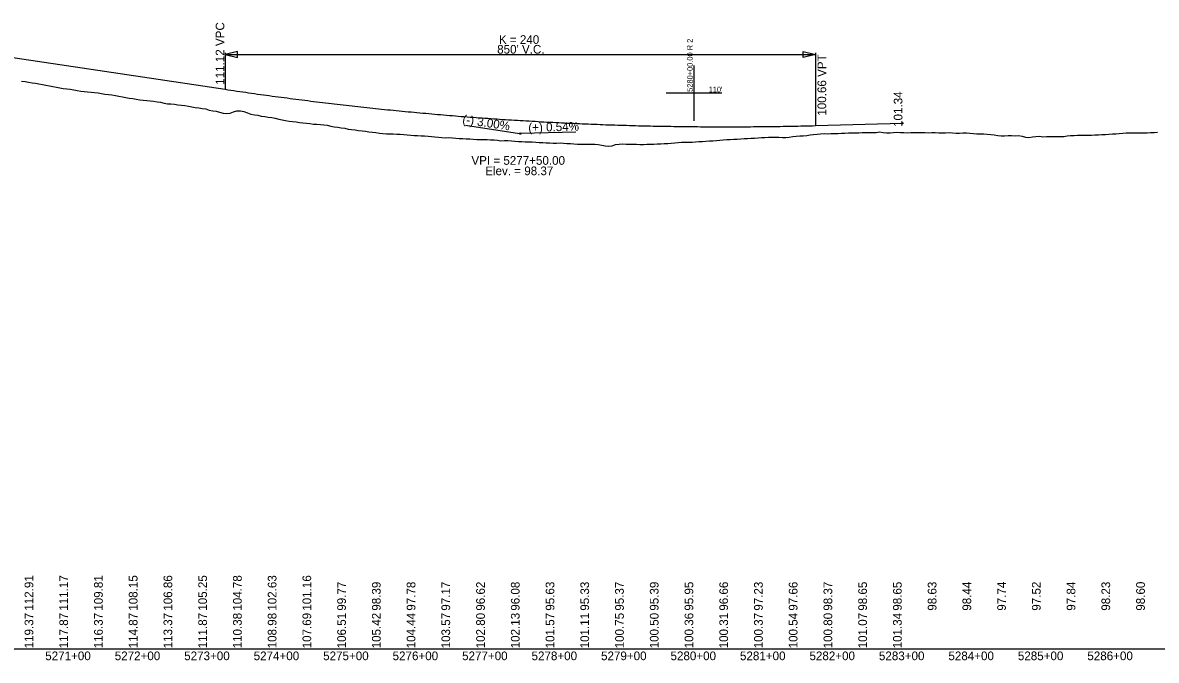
# Model space of a CAD drawing. Extents: x 2147288 to 2220488, y 740833 to 759333.
# Drawn here: x 2159415 to 2161047, y 750067 to 750985 of the extents above; entities that cross this region are included whole.
import ezdxf

# ---------------------------------------------------------------- set-up
doc = ezdxf.new("R2010")
doc.units = 0
for name, color, linetype in [('RD_DDB_GradeTX', 7, 'Continuous'), ('RD_DDB_Profile_EX', 7, 'Continuous'), ('RD_DDB_Profile_Lbl', 7, 'Continuous'), ('RD_DDB_Profile_PR', 7, 'Continuous'), ('RD_DDB_StaTX', 7, 'Continuous'), ('RD_DDB_StripGrade', 7, 'Continuous'), ('RD_DDB_VCLbl', 7, 'Continuous'), ('RD_GPK_Profile_Cell', 7, 'Continuous')]:
    doc.layers.add(name, color=color, linetype=linetype)

msp = doc.modelspace()

# ---------------------------------------------------------------- linework, layer by layer
at = {"layer": 'RD_DDB_GradeTX'}
for p, q in [((2160052, 750837.1), (2160130.1, 750825.4)), ((2160211.1, 750827.4), (2160132.1, 750825.3))]:
    msp.add_line(p, q, dxfattribs=at)
for centre in [(2160681.1, 750840.1), (2160131.1, 750825.3)]:
    msp.add_circle(centre, 1, dxfattribs=at)
at = {"layer": 'RD_DDB_Profile_EX'}
for points in [[(2159413.3, 750900.9), (2159418.3, 750900), (2159423.3, 750899.2), (2159428.3, 750898.4), (2159433.3, 750897.6), (2159438.3, 750896.8), (2159443.3, 750895.9), (2159448.3, 750894.9), (2159453.3, 750893.9), (2159458.3, 750892.8), (2159463.3, 750891.8), (2159468.3, 750891), (2159473.3, 750890.3), (2159478.3, 750889.7), (2159483.3, 750889), (2159488.3, 750888.2), (2159493.3, 750887.3), (2159498.3, 750886.4), (2159503.3, 750886), (2159508.3, 750885.5), (2159513.3, 750885), (2159518.3, 750884.5), (2159523.3, 750883.7), (2159528.3, 750882.9), (2159533.3, 750882.1), (2159538.3, 750881.5)], [(2159538.3, 750881.5), (2159543.3, 750880.8), (2159548.3, 750879.9), (2159553.3, 750878.9), (2159558.3, 750877.9), (2159563.3, 750877), (2159568.3, 750876.3), (2159573.3, 750875.6), (2159578.3, 750874.6), (2159583.3, 750873.8), (2159588.3, 750873.4), (2159593.3, 750872.9), (2159598.3, 750872.5), (2159603.3, 750871.9), (2159608.3, 750871.1), (2159613.3, 750870.2), (2159618.3, 750868.9), (2159623.3, 750867.8), (2159628.3, 750867.8), (2159633.3, 750867.7), (2159638.3, 750866.8), (2159643.3, 750866.1), (2159648.3, 750865.4), (2159653.3, 750864.6), (2159658.3, 750863.8), (2159663.3, 750862.9), (2159668.3, 750862.3), (2159673.3, 750861.5), (2159678.3, 750860.7), (2159683.3, 750858.9), (2159688.3, 750857.9), (2159693.3, 750857.3), (2159698.3, 750856.1), (2159703.3, 750854.5), (2159708.3, 750853.9), (2159713.3, 750854.7), (2159718.3, 750856.5), (2159723.3, 750857.8), (2159728.3, 750857.9), (2159733.3, 750856.8), (2159738.3, 750855.1), (2159743.3, 750853.1), (2159748.3, 750852.2), (2159753.3, 750851.5), (2159758.3, 750850.5), (2159763.3, 750849.6), (2159768.3, 750849), (2159773.3, 750848.2), (2159778.3, 750847.2), (2159783.3, 750846.1), (2159788.3, 750845), (2159793.3, 750844.2), (2159798.3, 750843.3), (2159803.3, 750842.6), (2159808.3, 750841.9), (2159813.3, 750841.4), (2159818.3, 750840.9), (2159823.3, 750840.4), (2159828.3, 750839.6), (2159833.3, 750839), (2159838.3, 750838.6), (2159843.3, 750838.2), (2159848.3, 750837.7), (2159853.3, 750837.1), (2159858.3, 750835.8), (2159863.3, 750834.9), (2159868.3, 750834.3), (2159873.3, 750833.5), (2159878.3, 750832.9), (2159883.3, 750831.8), (2159888.3, 750831.1), (2159893.3, 750830.5), (2159898.3, 750829.6), (2159903.3, 750829.1), (2159908.3, 750828.6), (2159913.3, 750827.7), (2159918.3, 750827.3), (2159923.3, 750826.8), (2159928.3, 750825.7), (2159933.3, 750825.1), (2159938.3, 750825), (2159943.3, 750824.8), (2159948.3, 750824.7), (2159953.3, 750824.5), (2159958.3, 750824.2), (2159963.3, 750823.7), (2159968.3, 750823.5), (2159973.3, 750822.8), (2159978.3, 750822.4), (2159983.3, 750822.3), (2159988.3, 750822.2), (2159993.3, 750821.8), (2159998.3, 750821.4), (2160003.3, 750821), (2160008.3, 750820.6), (2160013.3, 750820), (2160018.3, 750819.8), (2160023.3, 750819.3), (2160028.3, 750819.4), (2160033.3, 750819.1), (2160038.3, 750818.6)], [(2160538.3, 750822.2), (2160543.3, 750822.4), (2160548.3, 750823.3), (2160553.3, 750824.1), (2160558.3, 750824.3), (2160563.3, 750825), (2160568.3, 750825.4), (2160573.3, 750825), (2160578.3, 750825.1), (2160583.3, 750825.3), (2160588.3, 750825.5), (2160593.3, 750825.7), (2160598.3, 750826), (2160603.3, 750826.2), (2160608.3, 750826.2), (2160613.3, 750826.3), (2160618.3, 750826.5), (2160623.3, 750826.6), (2160628.3, 750826.7), (2160633.3, 750826.7), (2160638.3, 750826.7), (2160643.3, 750827), (2160648.3, 750827.5), (2160653.3, 750826.9), (2160658.3, 750826.4), (2160663.3, 750826.4), (2160668.3, 750826.6), (2160673.3, 750827.1), (2160678.3, 750826.7), (2160683.3, 750826.7), (2160688.3, 750826.5), (2160693.3, 750826.8), (2160698.3, 750827), (2160703.3, 750827), (2160708.3, 750826.9), (2160713.3, 750826.7), (2160718.3, 750826.5), (2160723.3, 750826.7), (2160728.3, 750826.7), (2160733.3, 750826.5), (2160738.3, 750826.4), (2160743.3, 750826.5), (2160748.3, 750826.6), (2160753.3, 750826.2), (2160758.3, 750826), (2160763.3, 750826), (2160768.3, 750826.2), (2160773.3, 750826.1), (2160778.3, 750825.8), (2160783.3, 750825.5), (2160788.3, 750825), (2160793.3, 750824.8), (2160798.3, 750824.8), (2160803.3, 750824.6), (2160808.3, 750823.9), (2160813.3, 750823.2), (2160818.3, 750822.5), (2160823.3, 750822.2), (2160828.3, 750821.9), (2160833.3, 750822.3), (2160838.3, 750822.4), (2160843.3, 750822.2), (2160848.3, 750822.5), (2160853.3, 750821.4), (2160858.3, 750819.9), (2160863.3, 750819.6), (2160868.3, 750820.3), (2160873.3, 750821), (2160878.3, 750821.5), (2160883.3, 750820.7), (2160888.3, 750820.8), (2160893.3, 750820.8), (2160898.3, 750820.8), (2160903.3, 750820.9), (2160908.3, 750820.8), (2160913.3, 750820.9), (2160918.3, 750821.8), (2160923.3, 750822.4), (2160928.3, 750822.6), (2160933.3, 750822.7), (2160938.3, 750822.8), (2160943.3, 750822.8), (2160948.3, 750822.8), (2160953.3, 750823.1), (2160958.3, 750823.3), (2160963.3, 750823.5), (2160968.3, 750823.8), (2160973.3, 750823.8), (2160978.3, 750824.4), (2160983.3, 750824.7), (2160988.3, 750824.9), (2160993.3, 750825.4), (2160998.3, 750825.8), (2161003.3, 750826.3), (2161008.3, 750826.2), (2161013.3, 750826.5), (2161018.3, 750826.5), (2161023.3, 750826.4), (2161028.3, 750826.3), (2161033.3, 750826.5), (2161038.3, 750826.8)], [(2161038.3, 750826.8), (2161043.3, 750827), (2161048.3, 750827.2)], [(2160038.3, 750818.6), (2160043.3, 750818.2), (2160048.3, 750817.9), (2160053.3, 750817.8), (2160058.3, 750817.6), (2160063.3, 750817.3), (2160068.3, 750816.9), (2160073.3, 750816.7), (2160078.3, 750816.6), (2160083.3, 750816.5), (2160088.3, 750816.3), (2160093.3, 750816), (2160098.3, 750815.5), (2160103.3, 750815), (2160108.3, 750815.1), (2160113.3, 750815.1), (2160118.3, 750814.7), (2160123.3, 750814.4), (2160128.3, 750814), (2160133.3, 750813.7), (2160138.3, 750813.4), (2160143.3, 750813.1), (2160148.3, 750813.1), (2160153.3, 750813), (2160158.3, 750812.5), (2160163.3, 750812.2), (2160168.3, 750812.1), (2160173.3, 750811.9), (2160178.3, 750811.6), (2160183.3, 750811.6), (2160188.3, 750811.7), (2160193.3, 750811.5), (2160198.3, 750811), (2160203.3, 750810.7), (2160208.3, 750810.4), (2160213.3, 750810.1), (2160218.3, 750809.9), (2160223.3, 750809.9), (2160228.3, 750810), (2160233.3, 750810.1), (2160238.3, 750809.9), (2160243.3, 750809.6), (2160248.3, 750808.5), (2160253.3, 750807.6), (2160258.3, 750807.2), (2160263.3, 750807.6), (2160268.3, 750809.3), (2160273.3, 750809.9), (2160278.3, 750810.5), (2160283.3, 750810.1), (2160288.3, 750809.9), (2160293.3, 750809.9), (2160298.3, 750809.8), (2160303.3, 750809.6), (2160308.3, 750809.7), (2160313.3, 750809.9), (2160318.3, 750810.1), (2160323.3, 750810.2), (2160328.3, 750810.3), (2160333.3, 750810.4), (2160338.3, 750810.7), (2160343.3, 750811), (2160348.3, 750811.5), (2160353.3, 750811.9), (2160358.3, 750812.6), (2160363.3, 750812.7), (2160368.3, 750812.7), (2160373.3, 750812.8), (2160378.3, 750813), (2160383.3, 750813.3), (2160388.3, 750813.7), (2160393.3, 750813.9), (2160398.3, 750814.2), (2160403.3, 750814.6), (2160408.3, 750814.9), (2160413.3, 750815.2), (2160418.3, 750815.6), (2160423.3, 750816), (2160428.3, 750816.5), (2160433.3, 750816.9), (2160438.3, 750817.2), (2160443.3, 750817.4), (2160448.3, 750817.8), (2160453.3, 750818.1), (2160458.3, 750818.2), (2160463.3, 750818.5), (2160468.3, 750818.6), (2160473.3, 750819), (2160478.3, 750819.4), (2160483.3, 750819.7), (2160488.3, 750820.1), (2160493.3, 750819.9), (2160498.3, 750820.2), (2160503.3, 750819.9), (2160508.3, 750819.4), (2160513.3, 750819.4), (2160518.3, 750820.2), (2160523.3, 750820.9), (2160528.3, 750821.5), (2160533.3, 750821.9), (2160538.3, 750822.2)]]:
    msp.add_lwpolyline(points, dxfattribs=at)
at = {"layer": 'RD_DDB_Profile_PR'}
for p, q in [((2159381.1, 750937.8), (2159706.1, 750889)), ((2160556.1, 750836.7), (2160681.1, 750840.1))]:
    msp.add_line(p, q, dxfattribs=at)
msp.add_spline([(2159706.1, 750889), (2159723.1, 750886.5), (2159740.1, 750884), (2159757.1, 750881.6), (2159774.1, 750879.3), (2159791.1, 750877), (2159808.1, 750874.8), (2159825.1, 750872.6), (2159842.1, 750870.5), (2159859.1, 750868.5), (2159876.1, 750866.5), (2159893.1, 750864.6), (2159910.1, 750862.7), (2159927.1, 750860.9), (2159944.1, 750859.2), (2159961.1, 750857.5), (2159978.1, 750855.9), (2159995.1, 750854.4), (2160012.1, 750852.9), (2160029.1, 750851.4), (2160046.1, 750850), (2160063.1, 750848.7), (2160080.1, 750847.5), (2160097.1, 750846.3), (2160114.1, 750845.1), (2160131.1, 750844.1), (2160148.1, 750843.1), (2160165.1, 750842.1), (2160182.1, 750841.2), (2160199.1, 750840.4), (2160216.1, 750839.6), (2160233.1, 750838.9), (2160250.1, 750838.2), (2160267.1, 750837.6), (2160284.1, 750837.1), (2160301.1, 750836.6), (2160318.1, 750836.2), (2160335.1, 750835.9), (2160352.1, 750835.6), (2160369.1, 750835.3), (2160386.1, 750835.2), (2160403.1, 750835), (2160420.1, 750835), (2160437.1, 750835), (2160454.1, 750835.1), (2160471.1, 750835.2), (2160488.1, 750835.4), (2160505.1, 750835.6), (2160522.1, 750835.9), (2160539.1, 750836.3), (2160556.1, 750836.7)], degree=3, dxfattribs=at)
at = {"layer": 'RD_DDB_VCLbl'}
for p, q in [((2159706.1, 750941.5), (2159706.1, 750889)), ((2159706.1, 750939), (2160556.1, 750939)), ((2160556.1, 750941.5), (2160556.1, 750836.7))]:
    msp.add_line(p, q, dxfattribs=at)
for points in [[(2159724.1, 750943.5), (2159706.1, 750939), (2159724.1, 750934.5)], [(2160538.1, 750943.5), (2160556.1, 750939), (2160538.1, 750934.5)]]:
    msp.add_lwpolyline(points, close=True, dxfattribs=at)
at = {"layer": 'RD_GPK_Profile_Cell'}
for p, q in [((2160381.1, 750923.4), (2160381.1, 750843.4)), ((2160421.1, 750883.4), (2160341.1, 750883.4)), ((2148888.3, 750083.4), (2170488.3, 750083.4))]:
    msp.add_line(p, q, dxfattribs=at)

# ---------------------------------------------------------------- texts
at = {"layer": 'RD_DDB_GradeTX'}
for s, rotation, p in [('(-) 3.00%', 351.4692, (2160047.2, 750839.9)), ('(+) 0.54%', 1.5466, (2160142.8, 750827.6))]:
    msp.add_text(s, height=12.5, rotation=rotation, dxfattribs=at).set_placement(p)
at = {"layer": 'RD_DDB_Profile_Lbl'}
msp.add_text('101.34', height=12.5, rotation=90, dxfattribs=at).set_placement((2160681.1, 750834.8))
for s, p in [('VPI = 5277+50.00', (2160060.7, 750780.3)), ('Elev. = 98.37', (2160080.6, 750765.3))]:
    msp.add_text(s, height=12.5, dxfattribs=at).set_placement(p)
at = {"layer": 'RD_DDB_StaTX'}
for s, p in [('5271+00', (2159447.3, 750067.2)), ('5272+00', (2159547.3, 750067.2)), ('5273+00', (2159647.3, 750067.2)), ('5274+00', (2159747.3, 750067.2)), ('5275+00', (2159847.3, 750067.2)), ('5276+00', (2159947.3, 750067.2)), ('5277+00', (2160047.3, 750067.2)), ('5278+00', (2160147.3, 750067.2)), ('5279+00', (2160247.3, 750067.2)), ('5280+00', (2160347.3, 750067.2)), ('5281+00', (2160447.3, 750067.2)), ('5282+00', (2160547.3, 750067.2)), ('5283+00', (2160647.3, 750067.2)), ('5284+00', (2160747.3, 750067.2)), ('5285+00', (2160847.3, 750067.2)), ('5286+00', (2160947.3, 750067.2))]:
    msp.add_text(s, height=12.5, dxfattribs=at).set_placement(p)
at = {"layer": 'RD_DDB_StripGrade'}
for s, p in [('111.12 VPC', (2159705.1, 750895.4)), ('100.66 VPT', (2160571.4, 750851)), ('112.91', (2159430.1, 750138.4)), ('111.17', (2159480.1, 750138.4)), ('109.81', (2159530.1, 750138.4)), ('108.15', (2159580.1, 750138.4)), ('106.86', (2159630.1, 750138.4)), ('105.25', (2159680.1, 750138.4)), ('104.78', (2159730.1, 750138.4)), ('102.63', (2159780.1, 750138.4)), ('101.16', (2159830.1, 750138.4)), ('99.77', (2159880.1, 750138.4)), ('98.39', (2159930.1, 750138.4)), ('97.78', (2159980.1, 750138.4)), ('97.17', (2160030.1, 750138.4)), ('96.62', (2160080.1, 750138.4)), ('96.08', (2160130.1, 750138.4)), ('95.63', (2160180.1, 750138.4)), ('95.33', (2160230.1, 750138.4)), ('95.37', (2160280.1, 750138.4)), ('95.39', (2160330.1, 750138.4)), ('95.95', (2160380.1, 750138.4)), ('96.66', (2160430.1, 750138.4)), ('97.23', (2160480.1, 750138.4)), ('97.66', (2160530.1, 750138.4)), ('98.37', (2160580.1, 750138.4)), ('98.65', (2160630.1, 750138.4)), ('98.65', (2160680.1, 750138.4)), ('98.63', (2160730.1, 750138.4)), ('98.44', (2160780.1, 750138.4)), ('97.74', (2160830.1, 750138.4)), ('97.52', (2160880.1, 750138.4)), ('97.84', (2160930.1, 750138.4)), ('98.23', (2160980.1, 750138.4)), ('98.60', (2161030.1, 750138.4)), ('119.37', (2159430.1, 750084.2)), ('117.87', (2159480.1, 750084.2)), ('116.37', (2159530.1, 750084.2)), ('114.87', (2159580.1, 750084.2)), ('113.37', (2159630.1, 750084.2)), ('111.87', (2159680.1, 750084.2)), ('110.38', (2159730.1, 750084.2)), ('108.98', (2159780.1, 750084.2)), ('107.69', (2159830.1, 750084.2)), ('106.51', (2159880.1, 750084.2)), ('105.42', (2159930.1, 750084.2)), ('104.44', (2159980.1, 750084.2)), ('103.57', (2160030.1, 750084.2)), ('102.80', (2160080.1, 750084.2)), ('102.13', (2160130.1, 750084.2)), ('101.57', (2160180.1, 750084.2)), ('101.11', (2160230.1, 750084.2)), ('100.75', (2160280.1, 750084.2)), ('100.50', (2160330.1, 750084.2)), ('100.36', (2160380.1, 750084.2)), ('100.31', (2160430.1, 750084.2)), ('100.37', (2160480.1, 750084.2)), ('100.54', (2160530.1, 750084.2)), ('100.80', (2160580.1, 750084.2)), ('101.07', (2160630.1, 750084.2)), ('101.34', (2160680.1, 750084.2))]:
    msp.add_text(s, height=12.5, rotation=90, dxfattribs=at).set_placement(p)
at = {"layer": 'RD_DDB_VCLbl'}
for s, p in [('K = 240', (2160100.3, 750954.3)), ("850' V.C.", (2160097.8, 750940.3))]:
    msp.add_text(s, height=12.5, dxfattribs=at).set_placement(p)
at = {"layer": 'RD_GPK_Profile_Cell'}
msp.add_text('5280+00.00 R 2', height=8, rotation=90, dxfattribs=at).set_placement((2160379.3, 750885.3))
msp.add_text("110'", height=8, dxfattribs=at).set_placement((2160402.2, 750884.6))

doc.saveas('drawing.dxf')
